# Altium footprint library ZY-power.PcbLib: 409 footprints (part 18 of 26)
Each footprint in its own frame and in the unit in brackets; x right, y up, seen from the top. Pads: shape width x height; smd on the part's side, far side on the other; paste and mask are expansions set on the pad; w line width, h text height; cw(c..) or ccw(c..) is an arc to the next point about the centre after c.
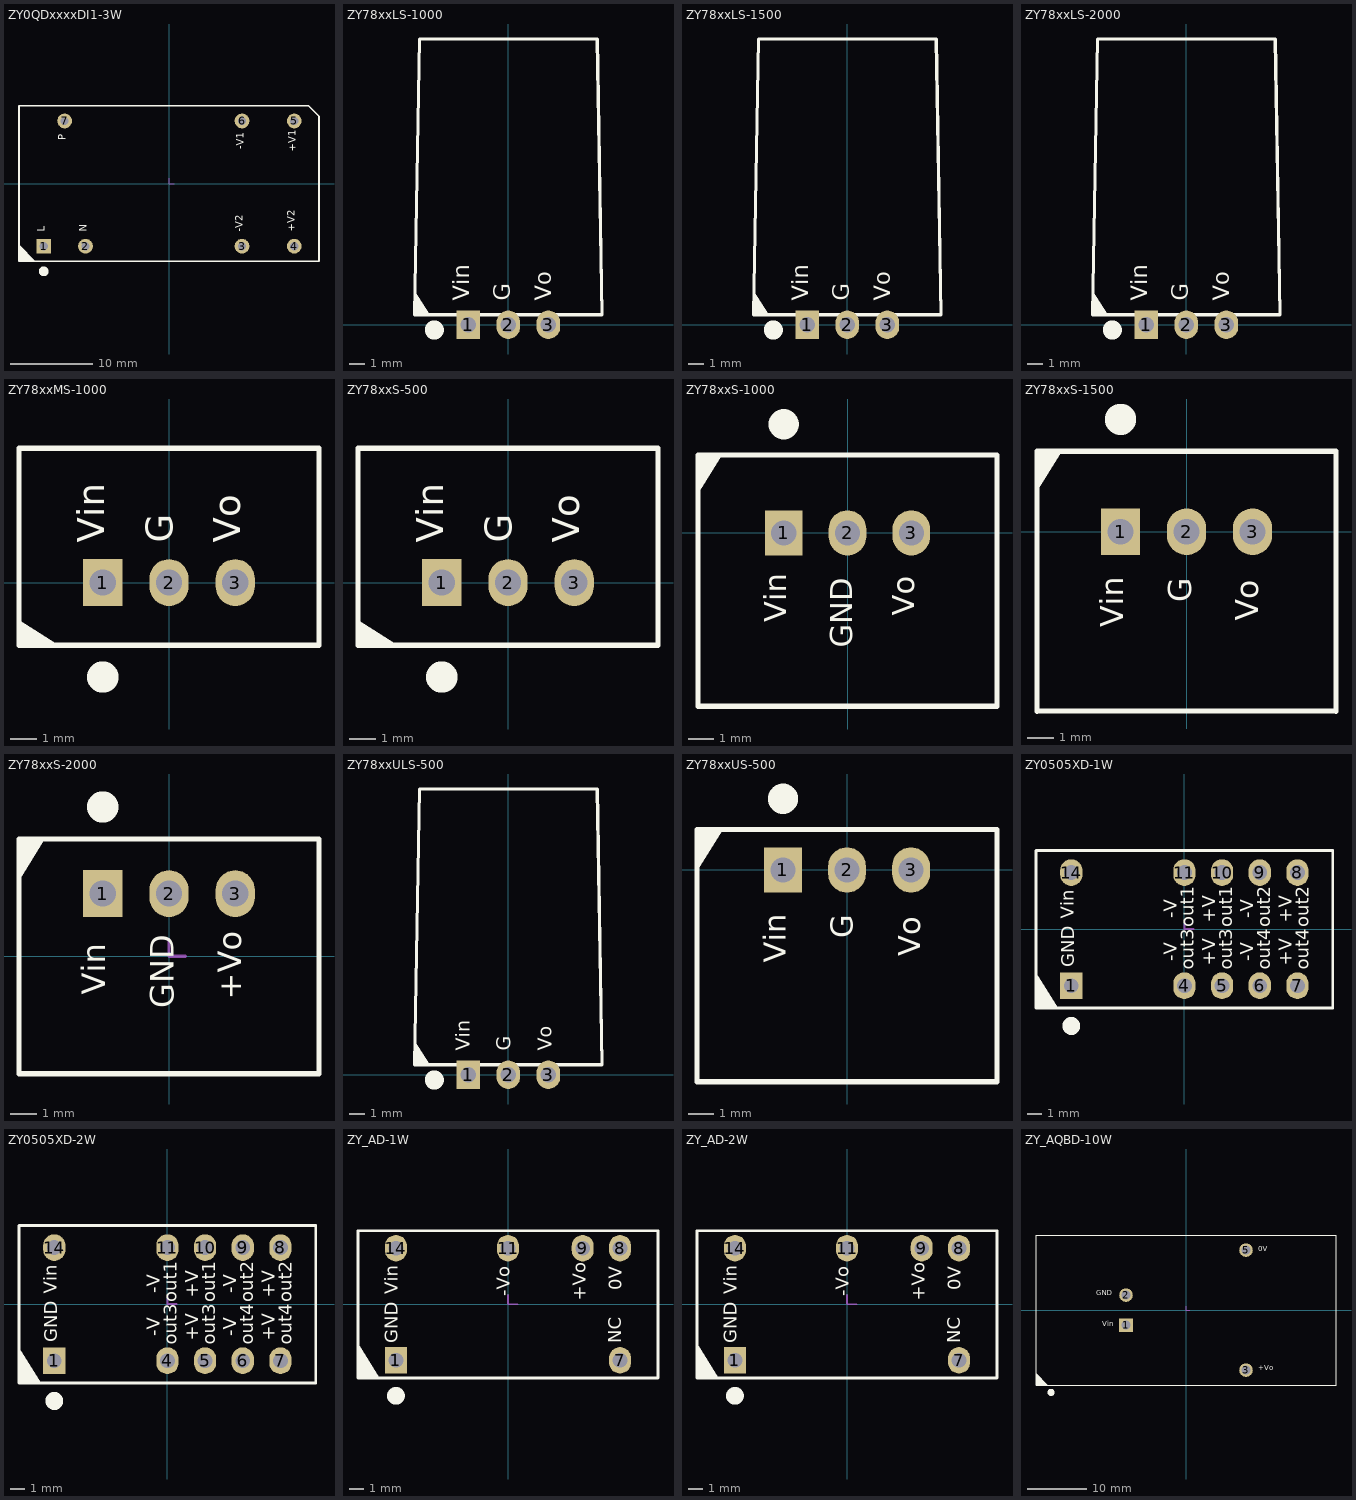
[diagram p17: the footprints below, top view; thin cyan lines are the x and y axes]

## ZY0QDxxxxDI1-3W [mm]
height 17.2
pads (7):
  rect 1.8x1.8 hole 1: 1(-15.24,-7.62)
  round 1.8 hole 1: 2(-10.16,-7.62) 3(8.89,-7.62) 4(15.24,-7.62) 5(15.24,7.62) 6(8.89,7.62) 7(-12.7,7.62)
Top Overlay:
  circle w1: c-15.245,-10.675 r0.1
  region: -18.25,-9.45 -16.275,-9.45 -18.25,-7.475
  lines w0.2: -18.25,-9.45 -18.25,9.45 16.98,9.45 18.25,8.18 18.25,-9.45 -18.25,-9.45
  text "P" at -12.268,5.281 h1.52
  text "L" at -14.808,-5.842 h1.52
  text "N" at -9.703,-5.842 h1.52
  text "-V2" at 9.296,-5.842 h1.52
  text "+V2" at 15.596,-5.842 h1.52
  text "+V1" at 15.697,3.886 h1.52
  text "-V1" at 9.398,4.198 h1.52
Mechanical 15:
  lines w0.127: 0,0.635 0,0 0.635,0

## ZY78xxLS-1000 [mm]
height 10
pads (3):
  rect 1.5x1.8 hole 1: 1(-2.54,0)
  oval 1.5x1.8 hole 1: 2(0,0) 3(2.54,0)
Top Overlay:
  circle w1: c-4.699,-0.327 r0.1
  region: -5.991,2.229 -5.991,0.644 -4.997,0.644
  lines w0.2: -5.95,0.644 5.95,0.644 5.645,18.144 -5.645,18.144 -5.95,0.644
  text "Vo" at 3.073,1.524 h1.78
  text "G" at 0.483,1.524 h1.78
  text "Vin" at -2.134,1.524 h1.78

## ZY78xxLS-1500 [mm]
height 10
pads (3):
  rect 1.5x1.8 hole 1: 1(-2.54,0)
  oval 1.5x1.8 hole 1: 2(0,0) 3(2.54,0)
Top Overlay:
  circle w1: c-4.699,-0.327 r0.1
  region: -5.991,2.229 -5.991,0.644 -4.997,0.644
  lines w0.2: -5.95,0.644 -5.645,18.144 5.645,18.144 5.95,0.644 -5.95,0.644
  text "Vin" at -2.134,1.524 h1.78
  text "G" at 0.483,1.524 h1.78
  text "Vo" at 3.073,1.524 h1.78

## ZY78xxLS-2000 [mm]
height 10
pads (3):
  rect 1.5x1.8 hole 1: 1(-2.54,0)
  oval 1.5x1.8 hole 1: 2(0,0) 3(2.54,0)
Top Overlay:
  circle w1: c-4.699,-0.327 r0.1
  region: -5.991,2.229 -5.991,0.644 -4.997,0.644
  lines w0.2: -5.95,0.644 5.95,0.644 5.645,18.144 -5.645,18.144 -5.95,0.644
  text "Vo" at 3.073,1.524 h1.78
  text "G" at 0.483,1.524 h1.78
  text "Vin" at -2.134,1.524 h1.78

## ZY78xxMS-1000 [mm]
height 10.2
pads (3):
  rect 1.5x1.8 hole 1: 1(-2.54,0)
  oval 1.5x1.8 hole 1: 2(0,0) 3(2.54,0)
Top Overlay:
  circle w1: c-2.54,-3.625 r0.1
  region: -4.168,-2.441 -5.753,-2.441 -5.753,-1.447
  lines w0.2: -5.753,-2.4 -5.753,5.15 5.753,5.15 5.753,-2.4 -5.753,-2.4
  text "Vo" at 3.073,1.524 h1.78
  text "G" at 0.483,1.524 h1.78
  text "Vin" at -2.134,1.524 h1.78

## ZY78xxS-500 [mm]
pads (3):
  rect 1.5x1.8 hole 1: 1(-2.54,0)
  oval 1.5x1.8 hole 1: 2(0,0) 3(2.54,0)
Top Overlay:
  circle w1: c-2.54,-3.625 r0.1
  region: -4.168,-2.441 -5.753,-2.441 -5.753,-1.447
  lines w0.2: -5.753,-2.4 5.753,-2.4 5.753,5.15 -5.753,5.15 -5.753,-2.4
  text "Vo" at 3.073,1.524 h1.78
  text "G" at 0.483,1.524 h1.78
  text "Vin" at -2.134,1.524 h1.78

## ZY78xxS-1000 [mm]
height 17.5
pads (3):
  rect 1.5x1.8 hole 1: 1(-2.54,0)
  oval 1.5x1.8 hole 1: 2(0,0) 3(2.54,0)
Top Overlay:
  circle w1: c-2.54,4.325 r0.1
  region: -5.991,1.514 -5.991,3.1 -4.997,3.1
  lines w0.2: -5.95,-6.9 -5.95,3.1 5.95,3.1 5.95,-6.9 -5.95,-6.9
  text "Vin" at -2.134,-3.562 h1.52
  text "GND" at 0.483,-4.572 h1.52
  text "Vo" at 2.946,-3.302 h1.52

## ZY78xxS-1500 [mm]
height 17.5
pads (3):
  rect 1.5x1.8 hole 1: 1(-2.54,0)
  oval 1.5x1.8 hole 1: 2(0,0) 3(2.54,0)
Top Overlay:
  circle w1: c-2.54,4.325 r0.1
  region: -5.794,1.514 -5.794,3.1 -4.801,3.1
  lines w0.2: -5.753,-6.908 -5.753,3.1 5.753,3.1 5.753,-6.908 ; -5.753,-6.9 5.753,-6.9
  text "Vo" at 3.073,-3.423 h1.52
  text "G" at 0.483,-2.714 h1.52
  text "Vin" at -2.134,-3.683 h1.52

## ZY78xxS-2000 [mm]
height 17.5
pads (3):
  rect 1.5x1.8 hole 1: 1(-2.54,2.4)
  oval 1.5x1.8 hole 1: 2(0,2.4) 3(2.54,2.4)
Top Overlay:
  circle w1: c-2.54,5.725 r0.1
  region: -5.75,2.914 -5.75,4.5 -4.756,4.5
  lines w0.2: -5.75,-4.5 5.75,-4.5 5.75,4.5 -5.75,4.5 -5.75,-4.5
  text "+Vo" at 3.073,-1.657 h1.52
  text "GND" at 0.483,-1.984 h1.52
  text "Vin" at -2.134,-1.477 h1.52
Mechanical 15:
  lines w0.127: 0,0.635 0,0 0.635,0

## ZY78xxULS-500 [mm]
height 10
pads (3):
  rect 1.5x1.8 hole 1: 1(-2.54,0)
  oval 1.5x1.8 hole 1: 2(0,0) 3(2.54,0)
Top Overlay:
  circle w1: c-4.699,-0.327 r0.1
  region: -5.991,2.229 -5.991,0.644 -4.997,0.644
  lines w0.2: -5.95,0.644 -5.645,18.144 5.645,18.144 5.95,0.644 -5.95,0.644
  text "Vin" at -2.134,1.524 h1.52
  text "G" at 0.483,1.524 h1.52
  text "Vo" at 3.073,1.524 h1.52

## ZY78xxUS-500 [mm]
height 17.5
pads (3):
  rect 1.5x1.8 hole 1: 1(-2.54,0)
  oval 1.5x1.8 hole 1: 2(0,0) 3(2.54,0)
Top Overlay:
  circle w1: c-2.54,2.825 r0.1
  region: -5.921,0.014 -5.921,1.6 -4.928,1.6
  lines w0.2: -5.95,-8.4 5.95,-8.4 5.95,1.6 -5.95,1.6 -5.95,-8.4
  text "Vo" at 3.2,-3.423 h1.52
  text "G" at 0.533,-2.714 h1.52
  text "Vin" at -2.134,-3.683 h1.52

## ZY0505XD-1W [mm]
height 8.5
pads (10):
  rect 1.5x1.8 hole 1: 1(-7.62,-3.81)
  oval 1.5x1.8 hole 1: 4(0,-3.81) 5(2.54,-3.81) 6(5.08,-3.81) 7(7.62,-3.81) 8(7.62,3.81) 9(5.08,3.81) 10(2.54,3.81) 11(0,3.81) 14(-7.62,3.81)
Top Overlay:
  circle w1: c-7.62,-6.525 r0.1
  region: -10,-2.97 -10,-5.3 -8.54,-5.3
  lines w0.2: -10,-5.3 -10,5.3 10,5.3 10,-5.3 -10,-5.3
  text "-V" at -0.196,0.746 h1.52
  text "out1" at 0.947,0.131 h1.52
  text "out1" at 3.538,0.131 h1.52
  text "+V" at 2.395,0.436 h1.52
  text "+V" at 7.551,0.436 h1.52
  text "out2" at 8.694,0.131 h1.52
  text "out2" at 6.104,0.131 h1.52
  text "-V" at 4.961,0.746 h1.52
  text "-V" at 4.961,-2.15 h1.52
  text "out4" at 6.104,-2.739 h1.52
  text "out4" at 8.694,-2.739 h1.52
  text "+V" at 7.551,-2.46 h1.52
  text "+V" at 2.395,-2.46 h1.52
  text "out3" at 3.538,-2.739 h1.52
  text "out3" at 0.947,-2.739 h1.52
  text "-V" at -0.196,-2.15 h1.52
  text "Vin" at -7.138,0.699 h1.52
  text "GND" at -7.13,-2.562 h1.52
Mechanical 15:
  lines w0.127: 0,0.635 0,0 0.635,0
3D body: height 0, standoff -4.91, extent -0.223,3.586 0.225,4.035
3D body: height 0, standoff -4.91, extent 2.317,3.586 2.765,4.035
3D body: height 0, standoff -4.91, extent 4.857,3.586 5.305,4.035
3D body: height 0, standoff -4.91, extent 7.397,3.586 7.845,4.035
3D body: height 0, standoff -4.91, extent 7.397,-4.034 7.845,-3.585
3D body: height 0, standoff -4.91, extent 4.857,-4.034 5.305,-3.585
3D body: height 0, standoff -4.91, extent 2.317,-4.034 2.765,-3.585
3D body: height 0, standoff -4.91, extent -0.223,-4.034 0.225,-3.585
3D body: height 0, standoff -4.91, extent -7.843,3.586 -7.395,4.035
3D body: height 0, standoff -4.91, extent -7.843,-4.034 -7.395,-3.585
3D body: height 8.5, standoff 0, extent -10,-5.3 10,5.3

## ZY0505XD-2W [mm]
height 8.5
pads (10):
  rect 1.5x1.8 hole 1: 1(-7.62,-3.81)
  oval 1.5x1.8 hole 1: 4(0,-3.81) 5(2.54,-3.81) 6(5.08,-3.81) 7(7.62,-3.81) 8(7.62,3.81) 9(5.08,3.81) 10(2.54,3.81) 11(0,3.81) 14(-7.62,3.81)
Top Overlay:
  circle w1: c-7.62,-6.525 r0.1
  region: -10,-2.97 -10,-5.3 -8.54,-5.3
  lines w0.2: -10,-5.3 10,-5.3 10,5.3 -10,5.3 -10,-5.3
  text "GND" at -7.13,-2.562 h1.52
  text "Vin" at -7.138,0.699 h1.52
  text "-V" at -0.196,-2.15 h1.52
  text "out3" at 0.947,-2.739 h1.52
  text "out3" at 3.538,-2.739 h1.52
  text "+V" at 2.395,-2.46 h1.52
  text "+V" at 7.551,-2.46 h1.52
  text "out4" at 8.694,-2.739 h1.52
  text "out4" at 6.104,-2.739 h1.52
  text "-V" at 4.961,-2.15 h1.52
  text "-V" at 4.961,0.746 h1.52
  text "out2" at 6.104,0.131 h1.52
  text "out2" at 8.694,0.131 h1.52
  text "+V" at 7.551,0.436 h1.52
  text "+V" at 2.395,0.436 h1.52
  text "out1" at 3.538,0.131 h1.52
  text "out1" at 0.947,0.131 h1.52
  text "-V" at -0.196,0.746 h1.52
Mechanical 15:
  lines w0.127: 0,0.635 0,0 0.635,0
3D body: height 8.5, standoff 0, extent -10,-5.3 10,5.3
3D body: height 0, standoff -4.91, extent -7.843,-4.034 -7.395,-3.585
3D body: height 0, standoff -4.91, extent -7.843,3.586 -7.395,4.035
3D body: height 0, standoff -4.91, extent -0.223,-4.034 0.225,-3.585
3D body: height 0, standoff -4.91, extent 2.317,-4.034 2.765,-3.585
3D body: height 0, standoff -4.91, extent 4.857,-4.034 5.305,-3.585
3D body: height 0, standoff -4.91, extent 7.397,-4.034 7.845,-3.585
3D body: height 0, standoff -4.91, extent 7.397,3.586 7.845,4.035
3D body: height 0, standoff -4.91, extent 4.857,3.586 5.305,4.035
3D body: height 0, standoff -4.91, extent 2.317,3.586 2.765,4.035
3D body: height 0, standoff -4.91, extent -0.223,3.586 0.225,4.035

## ZY_AD-1W [mm]
height 8.1
pads (6):
  rect 1.5x1.8 hole 1: 1(-7.62,-3.81)
  oval 1.5x1.8 hole 1: 7(7.62,-3.81) 8(7.62,3.81) 9(5.08,3.81) 11(0,3.81) 14(-7.62,3.81)
Top Overlay:
  circle w1: c-7.62,-6.225 r0.1
  region: -10.2,-2.67 -10.2,-5 -8.74,-5
  lines w0.2: -10.2,-5 10.2,-5 10.2,5 -10.2,5 -10.2,-5
  text "0V" at 8.052,0.967 h1.52
  text "+Vo" at 5.588,0.227 h1.52
  text "-Vo" at 0.432,0.539 h1.52
  text "Vin" at -7.188,0.695 h1.52
  text "NC" at 8.001,-2.667 h1.52
  text "GND" at -7.188,-2.667 h1.52
Mechanical 15:
  lines w0.127: 0,0.635 0,0 0.635,0

## ZY_AD-2W [mm]
height 8.1
pads (6):
  rect 1.5x1.8 hole 1: 1(-7.62,-3.81)
  oval 1.5x1.8 hole 1: 7(7.62,-3.81) 8(7.62,3.81) 9(5.08,3.81) 11(0,3.81) 14(-7.62,3.81)
Top Overlay:
  circle w1: c-7.62,-6.225 r0.1
  region: -10.2,-2.67 -10.2,-5 -8.74,-5
  lines w0.2: -10.2,-5 -10.2,5 10.2,5 10.2,-5 -10.2,-5
  text "GND" at -7.188,-2.667 h1.52
  text "NC" at 8.001,-2.667 h1.52
  text "Vin" at -7.188,0.695 h1.52
  text "-Vo" at 0.432,0.539 h1.52
  text "+Vo" at 5.588,0.227 h1.52
  text "0V" at 8.052,0.967 h1.52
Mechanical 15:
  lines w0.127: 0,0.635 0,0 0.635,0

## ZY_AQBD-10W [mm]
height 12.7
pads (4):
  rect 2.3x2.3 hole 1.5: 1(-10.16,-2.54)
  round 2.3 hole 1.5: 2(-10.16,2.54) 3(10.16,-10.16) 5(10.16,10.16)
Top Overlay:
  circle w1: c-22.86,-13.925 r0.1
  region: -25.4,-12.7 -23.425,-12.7 -25.4,-10.725
  lines w0.2: -25.4,-12.7 -25.4,12.7 25.4,12.7 25.4,-12.7 -25.4,-12.7
  text "+Vo" at 12.192,-10.541 h1.52
  text "0V" at 12.192,9.652 h1.52
  text "GND" at -15.189,2.159 h1.52
  text "Vin" at -14.179,-3.048 h1.52
Mechanical 15:
  lines w0.127: 0,0.635 0,0 0.635,0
